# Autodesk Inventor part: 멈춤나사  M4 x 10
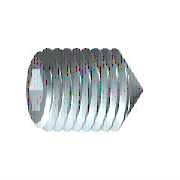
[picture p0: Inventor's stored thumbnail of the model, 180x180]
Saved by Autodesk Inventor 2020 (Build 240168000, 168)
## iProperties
Created: 2012-02
Part Number: 멈춤나사  M4 x 10
Material: 강철, 연강
Description: 6각 소켓 머리 없는 멈춤 나사
Document SubType Name: Modeling
Standard: KS B 1028
Designer: mduedu
Standards Organization: KS
Language: ko-KR
Size Designation: 원추점 M4x10
Categories: <MemberInstance><Categories><Category DisplayName="조임쇠" InternalName="e4da775c-781d-43d5-af7c-5136215cf5a6" Mnemonic="FSTN"><Category DisplayName="볼트" InternalN
Density: 7.86 g/cm^3
Mass: 0.792069 g
Surface Area: 1.48192 cm^2
Volume: 0.100772 cm^3
Appearance: 강철
Author: mduedu
IsCustomPart: 1
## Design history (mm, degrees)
sketch "스케치1"
  geometry: L1 (0, 0)-(6.833, 0); L2 (10, 1.155)-(10, 2); L3 (10, 2)-(0, 2); L4 (10, 1.155)-(7.5, 1.155); L5 (7.5, 1.155)-(6.833, 0); L6 (0, -0.4)-(0, 2.4) reference; L7 (0, 2)-(0, 0)
  constraints: 13 end point, 3 parallel, 1 collinear, 1 perpendicular, 1 point on line
  dimensions: "d0" = 2.5 distance of L2.start L4.end (= INTI); "d1" = 60 deg angle of L5 L1; "d2" = 4 diameter of L3 L1 (= NND); "d3" = 2.3094 diameter of L4 L1 (= 1.1547 x SW); "d5" = 10 distance from line of L2 L3.end (= NLG)
revolve "본체" sketch "스케치1" stored, may be unused: angle "d6" = 90 deg
sketch "스케치2"
  geometry: L1 (-0.577, 1)-(0.577, 1); L2 (0.577, 1)-(1.155, 0); L3 (1.155, 0)-(0.577, -1); L4 (0.577, -1)-(-0.577, -1); L5 (-0.577, -1)-(-1.155, 0); L6 (-1.155, 0)-(-0.577, 1); 3 further points
  constraints: 12 end point, 1 coincident, 1 horizontal, 13 other
extrude "슬롯" join sketch "스케치2" taper "d7" = 0 deg; stored distance "d21" = 10
workaxis "Work Axis1"
workplane "Work Plane1"
sketch "스케치4"
  geometry: L1 (-5, 0.2)-(-3.2, 2) reference; L2 (-5, -0.2)-(-3.2, -2) reference; L3 (-3.2, 2)-(-5.2, 0); L4 (-3.2, -2)-(-5.2, 0); 2 further points
  constraints: 4 end point, 2 collinear, 1 coincident
body "Solid1"
feature "스레드" dims "d12" = 10 (= NLG), "d13" = 0
chamfer "모따기1" distance "d8" = 1.8 (computed from NND, SPD, FAWI); stored, may be unused: angle "d9" = 45 deg (= FAWI), second distance "d34" = 1.8 (computed from NND, SPD, FAWI)
chamfer "모따기2" distance "d10" = 0.42941 (= -0.5 x GD1 + 0.5 x NND); stored, may be unused: angle "d11" = 45 deg (= FAWI), second distance "d35" = 0.42941 (= -0.5 x GD1 + 0.5 x NND)
other parameters: "NND" = 4 [user parameter; used in 5 equation terms], "NLG" = 10 [user parameter; used in 2 equation terms], "INTI" = 2.5 [user parameter; used in 1 equation term], "FAWI" = 45 deg [user parameter; used in 4 equation terms], "SW" = 2 [user parameter; used in 2 equation terms], "GD1" = 3.14117 (= THREADDIA - 1.2269 x PTC) [user parameter; used in 2 equation terms], "d4" = 0, "FAWI1" = 45 deg [user parameter], "SPD" = 0.4 [user parameter; used in 2 equation terms], "d36" = 0, "d37" = 0, "GUL" = 0.42941 (= 0.61345 x PTC) [user parameter], "TPU" = 14.28571 (computed from PTC) [user parameter], "TOA" = 30 deg [user parameter], "THREADDIA" = 4 [user parameter; used in 1 equation term], "PTC" = 0.7 [user parameter; used in 4 equation terms], "GAL" = 0.42941 (= 0.61345 x PTC) [user parameter], "E0" = 2.31 (= 1.155 x SW) [user parameter]
